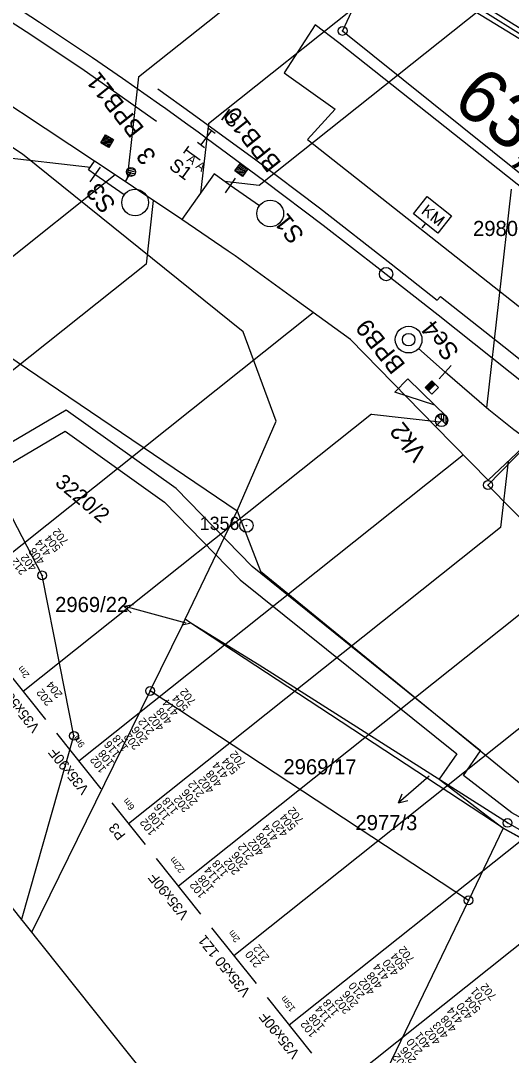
# Model space of a CAD drawing. Extents: x -620412 to -620034, y -1122986 to -1122565.
# Drawn here: x -620334.9 to -620279.8, y -1122770 to -1122653.6 of the extents above; entities that cross this region are included whole.
import ezdxf

# ---------------------------------------------------------------- set-up
doc = ezdxf.new("R2010")
doc.units = 0
for name, color, linetype in [('HranDP', 7, 'Continuous'), ('Hranice parcel', 7, 'Continuous'), ('Parcelní čísla', 7, 'Continuous'), ('Pop  PČ popisy', 7, 'Continuous'), ('Rámečky-tisk', 7, 'Continuous'), ('Vrstva 1', 7, 'Continuous'), ('Vrstva 14', 7, 'Continuous'), ('Vrstva 2', 7, 'Continuous'), ('Vrstva 3', 7, 'Continuous'), ('Vrstva 33', 7, 'Continuous'), ('Vrstva 4', 7, 'Continuous'), ('Vrstva 51', 7, 'Continuous'), ('Vrstva 6', 7, 'Continuous'), ('Vrstva 7', 7, 'Continuous'), ('Věcná břemena k části', 7, 'Continuous'), ('Značky bodu BP', 7, 'Continuous')]:
    doc.layers.add(name, color=color, linetype=linetype)

msp = doc.modelspace()

# ---------------------------------------------------------------- linework, layer by layer
at = {"layer": 'HranDP'}
for points in [[(-620310.57, -1122708.76), (-620306.2, -1122698.65), (-620309.9, -1122688.62), (-620334.71, -1122668.63), (-620384.5, -1122635.77)], [(-620296.23, -1122649.3), (-620298.73, -1122654.76), (-620265, -1122681.82), (-620263.22, -1122682.69), (-620260.55, -1122682.94), (-620253.83, -1122686.12), (-620245.73, -1122689.53), (-620242.51, -1122691.82), (-620225.75, -1122705.35), (-620226.24, -1122705.93)], [(-620310.57, -1122708.76), (-620307.94, -1122715.53), (-620278.65, -1122739.48), (-620275.74, -1122741.01)]]:
    msp.add_lwpolyline(points, dxfattribs=at)
at = {"layer": 'Hranice parcel'}
for p, q in [((-620316.42, -1122720.94), (-620310.57, -1122708.76)), ((-620316.74, -1122721.6), (-620316.42, -1122720.94)), ((-620315.79, -1122721.36), (-620316.42, -1122720.94)), ((-620320.37, -1122729), (-620316.74, -1122721.6)), ((-620315.79, -1122721.36), (-620316.74, -1122721.6)), ((-620280.66, -1122744.45), (-620315.79, -1122721.36)), ((-620320.37, -1122729), (-620333.7, -1122756.19)), ((-620284.57, -1122752.56), (-620320.37, -1122729)), ((-620334.83, -1122754.77), (-620328.93, -1122734.05)), ((-620280.66, -1122744.45), (-620284.57, -1122752.56)), ((-620246.32, -1122763.41), (-620280.66, -1122744.45)), ((-620284.57, -1122752.56), (-620304.19, -1122793.24))]:
    msp.add_line(p, q, dxfattribs=at)
for points in [[(-620310.57, -1122708.76), (-620306.2, -1122698.65), (-620309.9, -1122688.62), (-620334.71, -1122668.63), (-620384.5, -1122635.77)], [(-620397.41, -1122646.05), (-620368.46, -1122669.58), (-620310.57, -1122708.76)], [(-620296.23, -1122649.3), (-620298.73, -1122654.76), (-620265, -1122681.82), (-620263.22, -1122682.69), (-620260.55, -1122682.94), (-620253.83, -1122686.12), (-620245.73, -1122689.53), (-620242.51, -1122691.82), (-620225.75, -1122705.35), (-620226.24, -1122705.93)], [(-620302.66, -1122666.96), (-620267.81, -1122694.49), (-620266.86, -1122693.31), (-620261.82, -1122686.93), (-620261.22, -1122686.17), (-620299.15, -1122656.1), (-620301.83, -1122654.06), (-620305.28, -1122659.46), (-620299.56, -1122663.58), (-620302.66, -1122666.96)], [(-620328.93, -1122734.05), (-620330.51, -1122726.08), (-620332.51, -1122716.01), (-620337.56, -1122706.31), (-620342.37, -1122697.07)], [(-620264.06, -1122726.18), (-620263.28, -1122725.23), (-620282.38, -1122705.84), (-620278.07, -1122701.42), (-620246.12, -1122731.05)], [(-620310.57, -1122708.76), (-620307.94, -1122715.53), (-620278.65, -1122739.48), (-620275.74, -1122741.01)], [(-620243.2, -1122764.91), (-620246.23, -1122763.17), (-620280.18, -1122743.84), (-620308.1, -1122726.09), (-620315.79, -1122721.36)]]:
    msp.add_lwpolyline(points, dxfattribs=at)
at = {"layer": 'Pop  PČ popisy'}
for p, q in [((-620323.34, -1122719.48), (-620322.24, -1122719.26)), ((-620320.44, -1122720.26), (-620323.34, -1122719.48)), ((-620323.34, -1122719.48), (-620322.5, -1122720.23)), ((-620316.31, -1122721.37), (-620320.44, -1122720.26)), ((-620289.01, -1122738.58), (-620290.2, -1122739.63)), ((-620290.2, -1122739.63), (-620292.46, -1122741.6)), ((-620292.46, -1122741.6), (-620292.04, -1122740.56)), ((-620292.46, -1122741.6), (-620291.38, -1122741.32))]:
    msp.add_line(p, q, dxfattribs=at)
at = {"layer": 'Rámečky-tisk'}
msp.add_lwpolyline([(-620412.11, -1122657.76), (-620150.41, -1122986.26), (-620034.26, -1122893.74), (-620295.96, -1122565.23)], dxfattribs=at)
at = {"layer": 'Vrstva 1'}
for p, q in [((-620323.17, -1122671.7), (-620326.63, -1122669.41)), ((-620322.52, -1122670.62), (-620323.17, -1122671.7)), ((-620313.16, -1122670.85), (-620316.82, -1122675.99)), ((-620311.36, -1122672.15), (-620313.16, -1122670.85)), ((-620287.4, -1122698.35), (-620288.27, -1122699.25)), ((-620282.35, -1122705.3), (-620288.27, -1122699.25)), ((-620282.35, -1122705.3), (-620278.49, -1122701.64))]:
    msp.add_line(p, q, dxfattribs=at)
for points in [[(-620326.63, -1122669.41), (-620343.18, -1122658.46), (-620368.5, -1122642.9), (-620382.24, -1122633.97)], [(-620339.56, -1122649.37), (-620332.79, -1122653.78), (-620326.85, -1122657.77), (-620323.49, -1122660.07), (-620319.33, -1122663), (-620318.62, -1122663.49), (-620316.38, -1122665.1), (-620314.97, -1122666.12), (-620314.06, -1122666.78), (-620307.46, -1122671.65), (-620300.91, -1122676.61), (-620294.55, -1122681.56), (-620293.84, -1122682.11), (-620287.99, -1122686.71), (-620281.91, -1122691.52), (-620277.85, -1122694.74)], [(-620326.57, -1122670.9), (-620327.3, -1122670.38), (-620326.63, -1122669.41)], [(-620316.82, -1122675.99), (-620322.23, -1122672.32), (-620323.17, -1122671.7)], [(-620288.27, -1122699.25), (-620297.82, -1122689.49), (-620304.22, -1122684.86), (-620310.82, -1122680.06), (-620311.61, -1122679.52), (-620316.82, -1122675.99)], [(-620277.71, -1122700.9), (-620279.47, -1122699.65), (-620282.29, -1122697.37), (-620287.2, -1122693.16)]]:
    msp.add_lwpolyline(points, dxfattribs=at)
at = {"layer": 'Vrstva 14'}
msp.add_lwpolyline([(-620375.56, -1122628.64), (-620368.73, -1122632.95), (-620361.89, -1122637.25), (-620355.04, -1122641.55), (-620347.33, -1122646.47), (-620340.48, -1122650.8), (-620333.68, -1122655.25), (-620327.8, -1122659.17), (-620324.47, -1122661.49), (-620319.64, -1122664.92)], dxfattribs=at)
at = {"layer": 'Vrstva 2'}
for p, q in [((-620325.89, -1122667.3), (-620324.54, -1122666.95)), ((-620325.82, -1122667.42), (-620324.55, -1122667.09)), ((-620325.8, -1122667.14), (-620324.7, -1122666.86)), ((-620325.7, -1122666.98), (-620324.86, -1122666.76)), ((-620325.66, -1122667.51), (-620324.64, -1122667.25)), ((-620325.61, -1122666.82), (-620325.02, -1122666.67)), ((-620325.51, -1122666.66), (-620325.18, -1122666.57)), ((-620325.5, -1122667.6), (-620324.74, -1122667.41)), ((-620325.42, -1122666.5), (-620325.34, -1122666.48)), ((-620325.34, -1122667.7), (-620324.83, -1122667.57)), ((-620325.18, -1122667.79), (-620324.92, -1122667.73)), ((-620310.47, -1122669.99), (-620309.87, -1122669.9)), ((-620310.36, -1122669.84), (-620310.02, -1122669.79)), ((-620310.25, -1122669.69), (-620310.16, -1122669.68)), ((-620325.99, -1122670.08), (-620327.14, -1122671.72)), ((-620323.29, -1122673.19), (-620326.57, -1122670.9)), ((-620323.01, -1122670.53), (-620322.12, -1122670.32)), ((-620323.01, -1122670.74), (-620322.04, -1122670.5)), ((-620322.92, -1122670.92), (-620322.03, -1122670.71)), ((-620322.9, -1122670.3), (-620322.33, -1122670.16)), ((-620322.72, -1122671.08), (-620322.14, -1122670.94)), ((-620310.8, -1122670.44), (-620309.42, -1122670.24)), ((-620310.74, -1122670.56), (-620309.44, -1122670.37)), ((-620310.69, -1122670.29), (-620309.57, -1122670.13)), ((-620310.59, -1122670.67), (-620309.55, -1122670.52)), ((-620310.58, -1122670.14), (-620309.72, -1122670.01)), ((-620310.44, -1122670.78), (-620309.66, -1122670.67)), ((-620310.29, -1122670.9), (-620309.78, -1122670.82)), ((-620310.14, -1122671.01), (-620309.89, -1122670.97)), ((-620310.79, -1122671.33), (-620311.93, -1122672.96)), ((-620308.08, -1122674.44), (-620311.36, -1122672.15)), ((-620290.18, -1122690.49), (-620287.2, -1122693.16)), ((-620287.86, -1122693.9), (-620286.53, -1122692.41)), ((-620288.56, -1122694.26), (-620288.82, -1122694.26)), ((-620288.73, -1122694.92), (-620289.38, -1122694.93)), ((-620288.6, -1122694.79), (-620289.34, -1122694.8)), ((-620288.86, -1122695.05), (-620289.25, -1122695.06)), ((-620288.47, -1122694.65), (-620289.21, -1122694.66)), ((-620288.99, -1122695.19), (-620289.12, -1122695.19)), ((-620288.34, -1122694.52), (-620289.08, -1122694.53)), ((-620288.43, -1122694.39), (-620288.95, -1122694.4)), ((-620288.37, -1122696.84), (-620287.12, -1122698.06)), ((-620287.66, -1122697.86), (-620287.65, -1122698.52)), ((-620287.1, -1122699.05), (-620288.11, -1122698.07)), ((-620287.92, -1122697.93), (-620287.91, -1122698.26)), ((-620287.39, -1122697.9), (-620287.38, -1122698.78)), ((-620287.13, -1122698.05), (-620287.12, -1122699.04))]:
    msp.add_line(p, q, dxfattribs=at)
for points in [[(-620325.39, -1122666.45), (-620324.48, -1122666.98), (-620325.02, -1122667.89), (-620325.92, -1122667.35)], [(-620325.39, -1122666.45), (-620324.48, -1122666.98), (-620325.02, -1122667.89), (-620325.92, -1122667.35)], [(-620310.21, -1122669.65), (-620309.37, -1122670.27), (-620310, -1122671.12), (-620310.84, -1122670.49)], [(-620310.21, -1122669.65), (-620309.37, -1122670.27), (-620310, -1122671.12), (-620310.84, -1122670.49)], [(-620291.38, -1122693.9), (-620288.37, -1122696.84), (-620292.84, -1122695.41)], [(-620289.05, -1122695.25), (-620289.43, -1122694.88), (-620288.69, -1122694.13), (-620288.32, -1122694.5)], [(-620289.05, -1122695.25), (-620289.43, -1122694.88), (-620288.69, -1122694.13), (-620288.32, -1122694.5)], [(-620288.68, -1122695.62), (-620289.43, -1122694.88), (-620288.69, -1122694.13), (-620287.94, -1122694.86)]]:
    msp.add_lwpolyline(points, close=True, dxfattribs=at)
for centre, radius in [((-620322.52, -1122670.62), 0.5), ((-620322.06, -1122674.06), 1.5), ((-620306.86, -1122675.3), 1.5), ((-620291.3, -1122689.49), 1.5), ((-620291.3, -1122689.49), 0.7), ((-620287.6, -1122698.56), 0.7)]:
    msp.add_circle(centre, radius, dxfattribs=at)
msp.add_arc((-620287.6, -1122698.56), 0.7, 315.7256, 135.731, dxfattribs=at)
at = {"layer": 'Vrstva 3'}
for p, q in [((-620313.47, -1122665.98), (-620314.65, -1122667.59)), ((-620313.87, -1122665.68), (-620313.07, -1122666.27)), ((-620315.06, -1122667.29), (-620314.25, -1122667.88))]:
    msp.add_line(p, q, dxfattribs=at)
at = {"layer": 'Vrstva 33'}
for p, q in [((-620321.66, -1122659.92), (-620270.22, -1122618.94)), ((-620313.82, -1122665.18), (-620264.61, -1122625.98)), ((-620308.09, -1122672.12), (-620259, -1122633.02)), ((-620321.66, -1122659.92), (-620322.95, -1122671.32)), ((-620313.82, -1122665.18), (-620314.71, -1122673.02)), ((-620337.71, -1122668.87), (-620327.09, -1122670.07)), ((-620324.29, -1122670.96), (-620358.93, -1122698.56)), ((-620312.01, -1122671.68), (-620308.09, -1122672.12)), ((-620279.76, -1122672.57), (-620282.54, -1122697.17)), ((-620320.02, -1122673.82), (-620320.83, -1122680.99)), ((-620320.83, -1122680.99), (-620352.7, -1122706.39)), ((-620302.02, -1122686.47), (-620342.73, -1122718.9)), ((-620295.49, -1122697.88), (-620334.63, -1122729.07)), ((-620295.49, -1122697.88), (-620287.79, -1122698.75)), ((-620285.15, -1122702.43), (-620328.4, -1122736.89)), ((-620280.12, -1122703.19), (-620280.96, -1122710.6)), ((-620280.96, -1122710.6), (-620322.8, -1122743.93)), ((-620270.96, -1122714.14), (-620317.19, -1122750.97)), ((-620260.12, -1122718.29), (-620310.96, -1122758.79)), ((-620337.13, -1122725.94), (-620332.14, -1122732.2)), ((-620254.84, -1122726.87), (-620304.73, -1122766.61)), ((-620247.56, -1122732.58), (-620299.12, -1122773.65)), ((-620330.9, -1122733.76), (-620325.91, -1122740.02)), ((-620324.67, -1122741.58), (-620320.93, -1122746.27)), ((-620319.68, -1122747.84), (-620314.7, -1122754.1)), ((-620313.45, -1122755.66), (-620308.46, -1122761.92)), ((-620307.22, -1122763.48), (-620302.23, -1122769.74))]:
    msp.add_line(p, q, dxfattribs=at)
at = {"layer": 'Vrstva 4'}
msp.add_lwpolyline([(-620319.33, -1122663), (-620318.62, -1122663.49), (-620316.38, -1122665.1)], dxfattribs=at)
at = {"layer": 'Vrstva 51'}
msp.add_lwpolyline([(-620319.5, -1122661.29), (-620315.63, -1122664.05), (-620308.5, -1122669.28), (-620301.34, -1122674.65), (-620293.26, -1122680.96), (-620288.09, -1122685.04), (-620287.72, -1122684.65), (-620280.59, -1122690.26), (-620273.34, -1122696.07), (-620269.67, -1122699.33)], dxfattribs=at)
at = {"layer": 'Vrstva 6'}
for p, q in [((-620316.04, -1122667.72), (-620316.63, -1122668.53)), ((-620314.74, -1122669.3), (-620316.34, -1122668.13))]:
    msp.add_line(p, q, dxfattribs=at)
at = {"layer": 'Vrstva 7'}
for p, q in [((-620289.03, -1122674.33), (-620289.8, -1122675.32)), ((-620288.38, -1122674.85), (-620289.55, -1122674.99)), ((-620289.12, -1122674.94), (-620289.15, -1122675.83)), ((-620289.77, -1122676.92), (-620289.38, -1122676.43))]:
    msp.add_line(p, q, dxfattribs=at)
msp.add_lwpolyline([(-620290.75, -1122675.35), (-620289.22, -1122673.4), (-620286.48, -1122675.56), (-620288.01, -1122677.51)], close=True, dxfattribs=at)
msp.add_lwpolyline([(-620288.82, -1122676.09), (-620288.05, -1122675.11), (-620288.44, -1122676.38), (-620287.3, -1122675.69), (-620288.07, -1122676.67)], dxfattribs=at)
msp.add_circle((-620293.84, -1122682.11), 0.75, dxfattribs=at)
at = {"layer": 'Věcná břemena k části'}
msp.add_lwpolyline([(-620283.77, -1122648.8), (-620292.25, -1122641.75), (-620294.49, -1122646), (-620263.15, -1122665.23), (-620244.2, -1122676.01), (-620228.26, -1122687.89), (-620210.35, -1122702.87), (-620205.6, -1122706.65), (-620197.64, -1122718), (-620190.71, -1122730.68), (-620186.47, -1122727.64), (-620202.54, -1122702), (-620243.36, -1122670.23), (-620267.12, -1122661.31)], close=True, dxfattribs=at)
for points in [[(-620292.39, -1122646.54), (-620278.35, -1122655.35)], [(-620278.05, -1122654.95), (-620292.07, -1122646.16)], [(-620409.99, -1122656.07), (-620389.78, -1122673.21), (-620362.07, -1122697.07), (-620350.79, -1122712.11), (-620329.91, -1122699.79), (-620318.75, -1122707.75), (-620310.23, -1122716.49), (-620285.9, -1122736.09), (-620287.87, -1122738.92), (-620280.66, -1122744.45), (-620246.32, -1122763.41), (-620202.66, -1122784.39), (-620201.79, -1122782.59), (-620245.45, -1122761.61), (-620279.7, -1122742.7), (-620285.15, -1122738.52), (-620283.23, -1122735.73), (-620308.89, -1122715.01), (-620317.45, -1122706.23), (-620329.81, -1122697.41), (-620350.27, -1122709.47), (-620360.61, -1122695.69), (-620388.48, -1122671.69), (-620408.4, -1122654.8)]]:
    msp.add_lwpolyline(points, dxfattribs=at)
at = {"layer": 'Značky bodu BP'}
for centre, radius in [((-620298.73, -1122654.76), 0.5), ((-620298.73, -1122654.76), 0.0303), ((-620282.38, -1122705.84), 0.5), ((-620282.38, -1122705.84), 0.0303), ((-620309.54, -1122710.4), 0.75), ((-620309.54, -1122710.4), 0.03), ((-620332.51, -1122716.01), 0.5), ((-620332.51, -1122716.01), 0.0303), ((-620320.37, -1122729), 0.5), ((-620320.37, -1122729), 0.0303), ((-620328.93, -1122734.05), 0.5), ((-620328.93, -1122734.05), 0.0303), ((-620280.18, -1122743.84), 0.5), ((-620280.18, -1122743.84), 0.0303), ((-620284.57, -1122752.56), 0.5), ((-620284.57, -1122752.56), 0.0303)]:
    msp.add_circle(centre, radius, dxfattribs=at)

# ---------------------------------------------------------------- texts
at = {"layer": 'Parcelní čísla'}
for s, p in [('2980', (-620284.06, -1122677.83)), ('2969/22', (-620331.05, -1122720.13)), ('2969/17', (-620305.38, -1122738.38)), ('2977/3', (-620297.28, -1122744.66))]:
    msp.add_text(s, height=1.7, dxfattribs=at).set_placement(p)
msp.add_text('3220/2', height=1.7, rotation=320, dxfattribs=at).set_placement((-620331.16, -1122705.75))
at = {"layer": 'Vrstva 3'}
for s, height, rotation, p in [('BPB11', 2, 128.542, (-620320.95, -1122665.72)), ('IS', 1.5, 323.6053, (-620312.55, -1122664.62)), ('BPB10', 2, 128.542, (-620305.53, -1122669.62)), ('3', 2, 128.542, (-620319.59, -1122668.81)), ('S3', 2, 128.542, (-620324.12, -1122674.24)), ('S1', 2, 128.542, (-620302.93, -1122677.68)), ('BPB9', 2, 128.542, (-620291.58, -1122692.31)), ('Se4', 2, 128.542, (-620285.52, -1122690.83)), ('Vk2', 2, 128.542, (-620289.12, -1122702.19))]:
    msp.add_text(s, height=height, rotation=rotation, dxfattribs=at).set_placement(p)
at = {"layer": 'Vrstva 33'}
for s, height, p in [('702', 0.9, (-620329.48, -1122712.18)), ('504', 0.9, (-620330.36, -1122712.92)), ('408', 0.9, (-620332.16, -1122714.35)), ('414', 0.9, (-620331.44, -1122713.42)), ('212', 0.9, (-620334.18, -1122715.51)), ('402', 0.9, (-620333.06, -1122715.07)), ('V35x50 1Z1', 1.15, (-620332.7, -1122733.11)), ('2m', 0.75, (-620333.89, -1122727.19)), ('204', 0.9, (-620330.16, -1122729.38)), ('202', 0.9, (-620331.28, -1122730.23)), ('702', 0.9, (-620315.15, -1122730.17)), ('414', 0.9, (-620317.11, -1122731.41)), ('504', 0.9, (-620316.03, -1122730.91)), ('402', 0.9, (-620318.73, -1122733.06)), ('408', 0.9, (-620317.83, -1122732.34)), ('212', 0.9, (-620319.85, -1122733.5)), ('118', 0.9, (-620322.75, -1122735.4)), ('202', 0.9, (-620321.45, -1122735.18)), ('206', 0.9, (-620320.58, -1122734.44)), ('9m', 0.75, (-620327.66, -1122735.02)), ('116', 0.9, (-620323.67, -1122736.08)), ('V35x90F', 1.15, (-620327.16, -1122740.06)), ('102', 0.9, (-620325.25, -1122737.79)), ('108', 0.9, (-620324.35, -1122737.08)), ('702', 0.9, (-620309.55, -1122737.21)), ('414', 0.9, (-620311.5, -1122738.44)), ('504', 0.9, (-620310.43, -1122737.95)), ('402', 0.9, (-620313.12, -1122740.1)), ('408', 0.9, (-620312.23, -1122739.38)), ('212', 0.9, (-620314.24, -1122740.54)), ('202', 0.9, (-620315.85, -1122742.22)), ('206', 0.9, (-620314.97, -1122741.48)), ('6m', 0.75, (-620322.05, -1122742.06)), ('116', 0.9, (-620318.07, -1122743.12)), ('118', 0.9, (-620317.15, -1122742.43)), ('702', 0.9, (-620303.04, -1122743.53)), ('108', 0.9, (-620318.75, -1122744.12)), ('504', 0.9, (-620303.92, -1122744.27)), ('P3', 1.15, (-620323.06, -1122745.2)), ('102', 0.9, (-620319.65, -1122744.83)), ('414', 0.9, (-620305.89, -1122745.48)), ('420', 0.9, (-620304.82, -1122744.98)), ('408', 0.9, (-620306.62, -1122746.42)), ('212', 0.9, (-620308.64, -1122747.58)), ('402', 0.9, (-620307.52, -1122747.14)), ('22m', 0.75, (-620316.44, -1122749.1)), ('202', 0.9, (-620310.24, -1122749.26)), ('206', 0.9, (-620309.36, -1122748.52)), ('114', 0.9, (-620312.42, -1122750.22)), ('118', 0.9, (-620311.54, -1122749.47)), ('V35x90F', 1.15, (-620315.94, -1122754.14)), ('108', 0.9, (-620313.14, -1122751.16)), ('102', 0.9, (-620314.04, -1122751.87)), ('2m', 0.75, (-620310.21, -1122756.92)), ('V35x50 1Z1', 1.15, (-620309.02, -1122762.83)), ('210', 0.9, (-620307.81, -1122759.69)), ('212', 0.9, (-620306.9, -1122758.98)), ('702', 0.9, (-620290.58, -1122759.18)), ('420', 0.9, (-620292.36, -1122760.63)), ('504', 0.9, (-620291.46, -1122759.92)), ('408', 0.9, (-620294.16, -1122762.07)), ('414', 0.9, (-620293.43, -1122761.13)), ('210', 0.9, (-620296.18, -1122763.21)), ('402', 0.9, (-620295.06, -1122762.78)), ('702', 0.9, (-620281.37, -1122763.35)), ('206', 0.9, (-620296.9, -1122764.16)), ('701', 0.9, (-620282.47, -1122763.81)), ('15m', 0.75, (-620303.98, -1122764.74)), ('118', 0.9, (-620299.08, -1122765.12)), ('202', 0.9, (-620297.78, -1122764.9)), ('420', 0.9, (-620284.05, -1122765.52)), ('504', 0.9, (-620283.15, -1122764.81)), ('V35x90F', 1.15, (-620303.48, -1122769.78)), ('108', 0.9, (-620300.68, -1122766.8)), ('114', 0.9, (-620299.95, -1122765.86)), ('414', 0.9, (-620285.13, -1122766.02)), ('102', 0.9, (-620301.58, -1122767.52)), ('403', 0.9, (-620286.75, -1122767.67)), ('408', 0.9, (-620285.85, -1122766.96)), ('401', 0.9, (-620288.75, -1122768.85)), ('402', 0.9, (-620287.65, -1122768.39)), ('210', 0.9, (-620289.68, -1122769.54)), ('202', 0.9, (-620291.27, -1122771.23)), ('206', 0.9, (-620290.39, -1122770.48))]:
    msp.add_text(s, height=height, rotation=128.542, dxfattribs=at).set_placement(p)
at = {"layer": 'Vrstva 6'}
for s, height, p in [('S1', 1.5, (-620318.35, -1122670.18)), ('  A A ', 1, (-620316.93, -1122668.93))]:
    msp.add_text(s, height=height, rotation=323.6053, dxfattribs=at).set_placement(p)
at = {"layer": 'Vrstva 7'}
msp.add_text('63,4', height=6, rotation=321.8255, dxfattribs=at).set_placement((-620286.61, -1122663.08))
at = {"layer": 'Značky bodu BP'}
msp.add_text('1356', height=1.5, dxfattribs=at).set_placement((-620314.79, -1122710.9))

doc.saveas('drawing.dxf')
